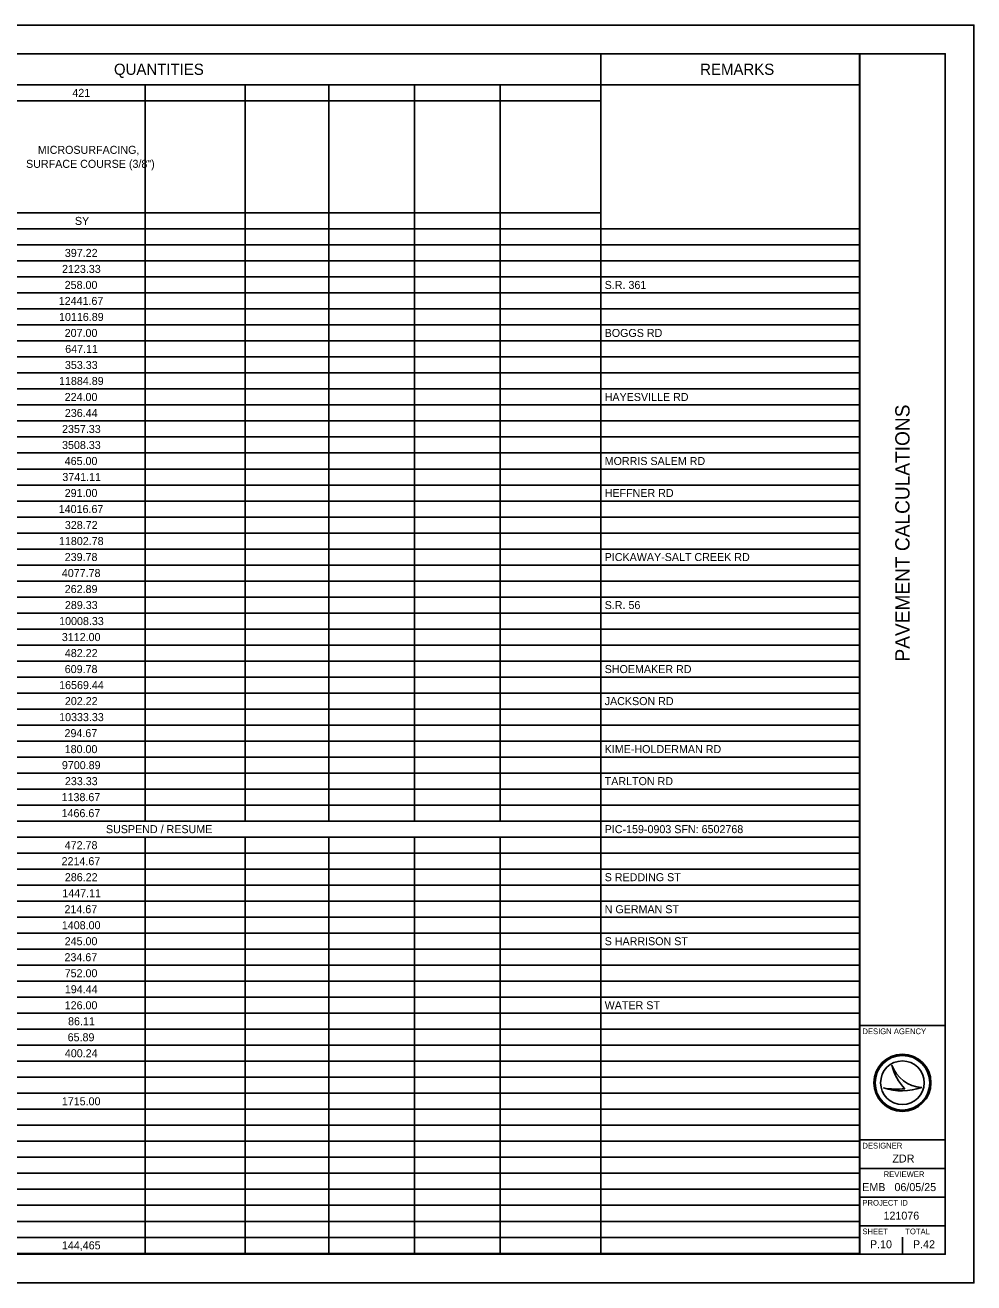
# Model space of a CAD drawing. Extents: x 0 to 34, y 0 to 22.
# Drawn here: x 17.4 to 34, y 0 to 22 of the extents above; entities that cross this region are included whole.
import ezdxf

# ---------------------------------------------------------------- set-up
doc = ezdxf.new("R2010")
doc.units = 0
for name, color, linetype in [('SH_Border', 7, 'Continuous'), ('SH_Cut_Line', 7, 'Continuous'), ('SH_Data', 7, 'Continuous'), ('SH_Text', 7, 'Continuous')]:
    doc.layers.add(name, color=color, linetype=linetype)

msp = doc.modelspace()

# ---------------------------------------------------------------- linework, layer by layer
at = {"layer": 'SH_Border'}
for p, q in [((32, 0.5), (32, 21.5)), ((32, 4.5), (33.5, 4.5)), ((32, 2.5), (33.5, 2.5)), ((32, 2), (33.5, 2)), ((32, 1.5), (33.5, 1.5)), ((32, 1), (33.5, 1))]:
    msp.add_line(p, q, dxfattribs=at)
msp.add_lwpolyline([(1.5, 21.5), (33.5, 21.5), (33.5, 0.5), (1.5, 0.5)], close=True, dxfattribs=at)
at = {"layer": 'SH_Cut_Line'}
msp.add_lwpolyline([(0, 0), (34, 0), (34, 22), (0, 22)], close=True, dxfattribs=at)
at = {"layer": 'SH_Data'}
for p, q in [((32.567, 3.81), (32.567, 3.81)), ((32.417, 3.41), (32.417, 3.41)), ((32.75, 3.5), (32.75, 3.5)), ((33.087, 3.419), (33.087, 3.419)), ((32.375, 0.675), (32.375, 0.675)), ((32.75, 0.5), (32.75, 0.8))]:
    msp.add_line(p, q, dxfattribs=at)
for radius in [0.5, 0.477, 0.477, 0.382]:
    msp.add_circle((32.75, 3.5), radius, dxfattribs=at)
for centre, radius, start, end in [((33.116, 3.998), 0.58, 198.9257, 198.9319), ((33.347, 3.97), 0.796, 191.6379, 191.6421), ((33.116, 3.998), 0.58, 198.9319, 267.1657), ((33.347, 3.97), 0.796, 191.6421, 226.0947), ((32.739, 4.37), 1.013, 251.4576, 290.0832), ((32.648, 4.654), 1.266, 259.4964, 259.4995), ((32.739, 4.37), 1.013, 251.4527, 251.4576), ((32.648, 4.654), 1.266, 259.4995, 276.6672)]:
    msp.add_arc(centre, radius, start, end, dxfattribs=at)
at = {"layer": 'SH_Text'}
for p, q in [((1.5, 21.5), (32.004, 21.5)), ((27.474, 21.5), (27.474, 0.516)), ((32.004, 21.5), (32.004, 0.516)), ((1.5, 20.956), (32.004, 20.956)), ((19.502, 20.956), (19.502, 8.076)), ((21.248, 20.956), (21.248, 8.076)), ((22.714, 20.956), (22.714, 8.076)), ((24.213, 20.956), (24.213, 8.076)), ((25.712, 20.956), (25.712, 8.076)), ((11.745, 20.676), (27.474, 20.676)), ((9.636, 18.716), (27.474, 18.716)), ((1.5, 18.436), (32.004, 18.436)), ((1.5, 18.156), (32.004, 18.156)), ((1.5, 17.876), (32.004, 17.876)), ((1.5, 17.596), (32.004, 17.596)), ((1.5, 17.316), (32.004, 17.316)), ((1.5, 17.036), (32.004, 17.036)), ((1.5, 16.756), (32.004, 16.756)), ((1.5, 16.476), (32.004, 16.476)), ((1.5, 16.196), (32.004, 16.196)), ((1.5, 15.916), (32.004, 15.916)), ((1.5, 15.636), (32.004, 15.636)), ((1.5, 15.356), (32.004, 15.356)), ((1.5, 15.076), (32.004, 15.076)), ((1.5, 14.796), (32.004, 14.796)), ((1.5, 14.516), (32.004, 14.516)), ((1.5, 14.236), (32.004, 14.236)), ((1.5, 13.956), (32.004, 13.956)), ((1.5, 13.676), (32.004, 13.676)), ((1.5, 13.396), (32.004, 13.396)), ((1.5, 13.116), (32.004, 13.116)), ((1.5, 12.836), (32.004, 12.836)), ((1.5, 12.556), (32.004, 12.556)), ((1.5, 12.276), (32.004, 12.276)), ((1.5, 11.996), (32.004, 11.996)), ((1.5, 11.716), (32.004, 11.716)), ((1.5, 11.436), (32.004, 11.436)), ((1.5, 11.156), (32.004, 11.156)), ((1.5, 10.876), (32.004, 10.876)), ((1.5, 10.596), (32.004, 10.596)), ((1.5, 10.316), (32.004, 10.316)), ((1.5, 10.036), (32.004, 10.036)), ((1.5, 9.756), (32.004, 9.756)), ((1.5, 9.476), (32.004, 9.476)), ((1.5, 9.196), (32.004, 9.196)), ((1.5, 8.916), (32.004, 8.916)), ((1.5, 8.636), (32.004, 8.636)), ((1.5, 8.356), (32.004, 8.356)), ((1.5, 8.076), (32.004, 8.076)), ((1.5, 7.796), (32.004, 7.796)), ((19.502, 7.796), (19.502, 0.516)), ((21.248, 7.796), (21.248, 0.516)), ((22.714, 7.796), (22.714, 0.516)), ((24.213, 7.796), (24.213, 0.516)), ((25.712, 7.796), (25.712, 0.516)), ((1.5, 7.516), (32.004, 7.516)), ((1.5, 7.236), (32.004, 7.236)), ((1.5, 6.956), (32.004, 6.956)), ((1.5, 6.676), (32.004, 6.676)), ((1.5, 6.396), (32.004, 6.396)), ((1.5, 6.116), (32.004, 6.116)), ((1.5, 5.836), (32.004, 5.836)), ((1.5, 5.556), (32.004, 5.556)), ((1.5, 5.276), (32.004, 5.276)), ((1.5, 4.996), (32.004, 4.996)), ((1.5, 4.716), (32.004, 4.716)), ((1.5, 4.436), (32.004, 4.436)), ((1.5, 4.156), (32.004, 4.156)), ((1.5, 3.876), (32.004, 3.876)), ((1.5, 3.596), (32.004, 3.596)), ((1.5, 3.316), (32.004, 3.316)), ((1.5, 3.036), (32.004, 3.036)), ((1.5, 2.756), (32.004, 2.756)), ((1.5, 2.476), (32.004, 2.476)), ((1.5, 2.196), (32.004, 2.196)), ((1.5, 1.916), (32.004, 1.916)), ((1.5, 1.636), (32.004, 1.636)), ((1.5, 1.356), (32.004, 1.356)), ((1.5, 1.076), (32.004, 1.076)), ((1.5, 0.796), (32.004, 0.796)), ((1.5, 0.516), (32.004, 0.516))]:
    msp.add_line(p, q, dxfattribs=at)

# ---------------------------------------------------------------- texts
at = {"layer": 'SH_Data'}
msp.add_text('PAVEMENT CALCULATIONS', height=0.25, rotation=90, dxfattribs=at).set_placement((32.875, 10.868))
for s, height, p in [('DESIGN AGENCY', 0.1, (32.05, 4.35)), ('DESIGNER', 0.1, (32.05, 2.35)), ('ZDR', 0.14, (32.575, 2.105)), ('REVIEWER', 0.1, (32.422, 1.85)), ('EMB', 0.14, (32.047, 1.605)), ('06/05/25', 0.14, (32.611, 1.605)), ('PROJECT ID', 0.1, (32.05, 1.35)), ('121076', 0.14, (32.419, 1.105)), ('SHEET', 0.1, (32.05, 0.85)), ('TOTAL', 0.1, (32.8, 0.85)), ('P.10', 0.14, (32.182, 0.605)), ('P.42', 0.14, (32.935, 0.605))]:
    msp.add_text(s, height=height, dxfattribs=at).set_placement(p)
at = {"layer": 'SH_Text'}
for s, height, p in [('QUANTITIES', 0.196, (18.953, 21.13)), ('REMARKS', 0.196, (29.211, 21.13)), ('421', 0.14, (18.225, 20.746)), ('MICROSURFACING, ', 0.14, (17.62, 19.749)), ('SURFACE COURSE (3/8")', 0.14, (17.415, 19.504)), ('SY', 0.14, (18.27, 18.506)), ('397.22', 0.14, (18.094, 17.946)), ('2123.33', 0.14, (18.045, 17.666)), ('258.00', 0.14, (18.091, 17.386)), ('S.R. 361', 0.14, (27.54, 17.386)), ('12441.67', 0.14, (17.987, 17.106)), ('10116.89', 0.14, (17.992, 16.826)), ('207.00', 0.14, (18.091, 16.546)), ('BOGGS RD', 0.14, (27.54, 16.546)), ('647.11', 0.14, (18.1, 16.266)), ('353.33', 0.14, (18.095, 15.986)), ('11884.89', 0.14, (17.992, 15.706)), ('224.00', 0.14, (18.091, 15.426)), ('HAYESVILLE RD', 0.14, (27.54, 15.426)), ('236.44', 0.14, (18.094, 15.146)), ('2357.33', 0.14, (18.045, 14.866)), ('3508.33', 0.14, (18.045, 14.586)), ('465.00', 0.14, (18.091, 14.306)), ('MORRIS SALEM RD', 0.14, (27.54, 14.306)), ('3741.11', 0.14, (18.05, 14.026)), ('291.00', 0.14, (18.091, 13.746)), ('HEFFNER RD', 0.14, (27.54, 13.746)), ('14016.67', 0.14, (17.987, 13.466)), ('328.72', 0.14, (18.094, 13.186)), ('11802.78', 0.14, (17.991, 12.906)), ('239.78', 0.14, (18.092, 12.626)), ('PICKAWAY-SALT CREEK RD', 0.14, (27.54, 12.626)), ('4077.78', 0.14, (18.041, 12.346)), ('262.89', 0.14, (18.092, 12.066)), ('289.33', 0.14, (18.095, 11.786)), ('S.R. 56', 0.14, (27.54, 11.786)), ('10008.33', 0.14, (17.994, 11.506)), ('3112.00', 0.14, (18.041, 11.226)), ('482.22', 0.14, (18.094, 10.946)), ('609.78', 0.14, (18.092, 10.666)), ('SHOEMAKER RD', 0.14, (27.54, 10.666)), ('16569.44', 0.14, (17.994, 10.386)), ('202.22', 0.14, (18.094, 10.106)), ('JACKSON RD', 0.14, (27.54, 10.106)), ('10333.33', 0.14, (17.994, 9.826)), ('294.67', 0.14, (18.088, 9.546)), ('180.00', 0.14, (18.091, 9.266)), ('KIME-HOLDERMAN RD', 0.14, (27.54, 9.266)), ('9700.89', 0.14, (18.042, 8.986)), ('233.33', 0.14, (18.095, 8.706)), ('TARLTON RD', 0.14, (27.54, 8.706)), ('1138.67', 0.14, (18.037, 8.426)), ('1466.67', 0.14, (18.037, 8.146)), ('SUSPEND / RESUME', 0.14, (18.813, 7.866)), ('PIC-159-0903 SFN: 6502768', 0.14, (27.54, 7.866)), ('472.78', 0.14, (18.092, 7.586)), ('2214.67', 0.14, (18.037, 7.306)), ('286.22', 0.14, (18.094, 7.026)), ('S REDDING ST', 0.14, (27.54, 7.026)), ('1447.11', 0.14, (18.05, 6.746)), ('214.67', 0.14, (18.088, 6.466)), ('N GERMAN ST', 0.14, (27.54, 6.466)), ('1408.00', 0.14, (18.041, 6.186)), ('245.00', 0.14, (18.091, 5.906)), ('S HARRISON ST', 0.14, (27.54, 5.906)), ('234.67', 0.14, (18.088, 5.626)), ('752.00', 0.14, (18.091, 5.346)), ('194.44', 0.14, (18.094, 5.066)), ('126.00', 0.14, (18.091, 4.786)), ('WATER ST', 0.14, (27.54, 4.786)), ('86.11', 0.14, (18.15, 4.506)), ('65.89', 0.14, (18.143, 4.226)), ('400.24', 0.14, (18.094, 3.946)), ('1715.00', 0.14, (18.041, 3.106)), ('144,465', 0.14, (18.043, 0.586))]:
    msp.add_text(s, height=height, dxfattribs=at).set_placement(p)

doc.saveas('drawing.dxf')
